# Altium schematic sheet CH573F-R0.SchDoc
size 330 x 220 mm
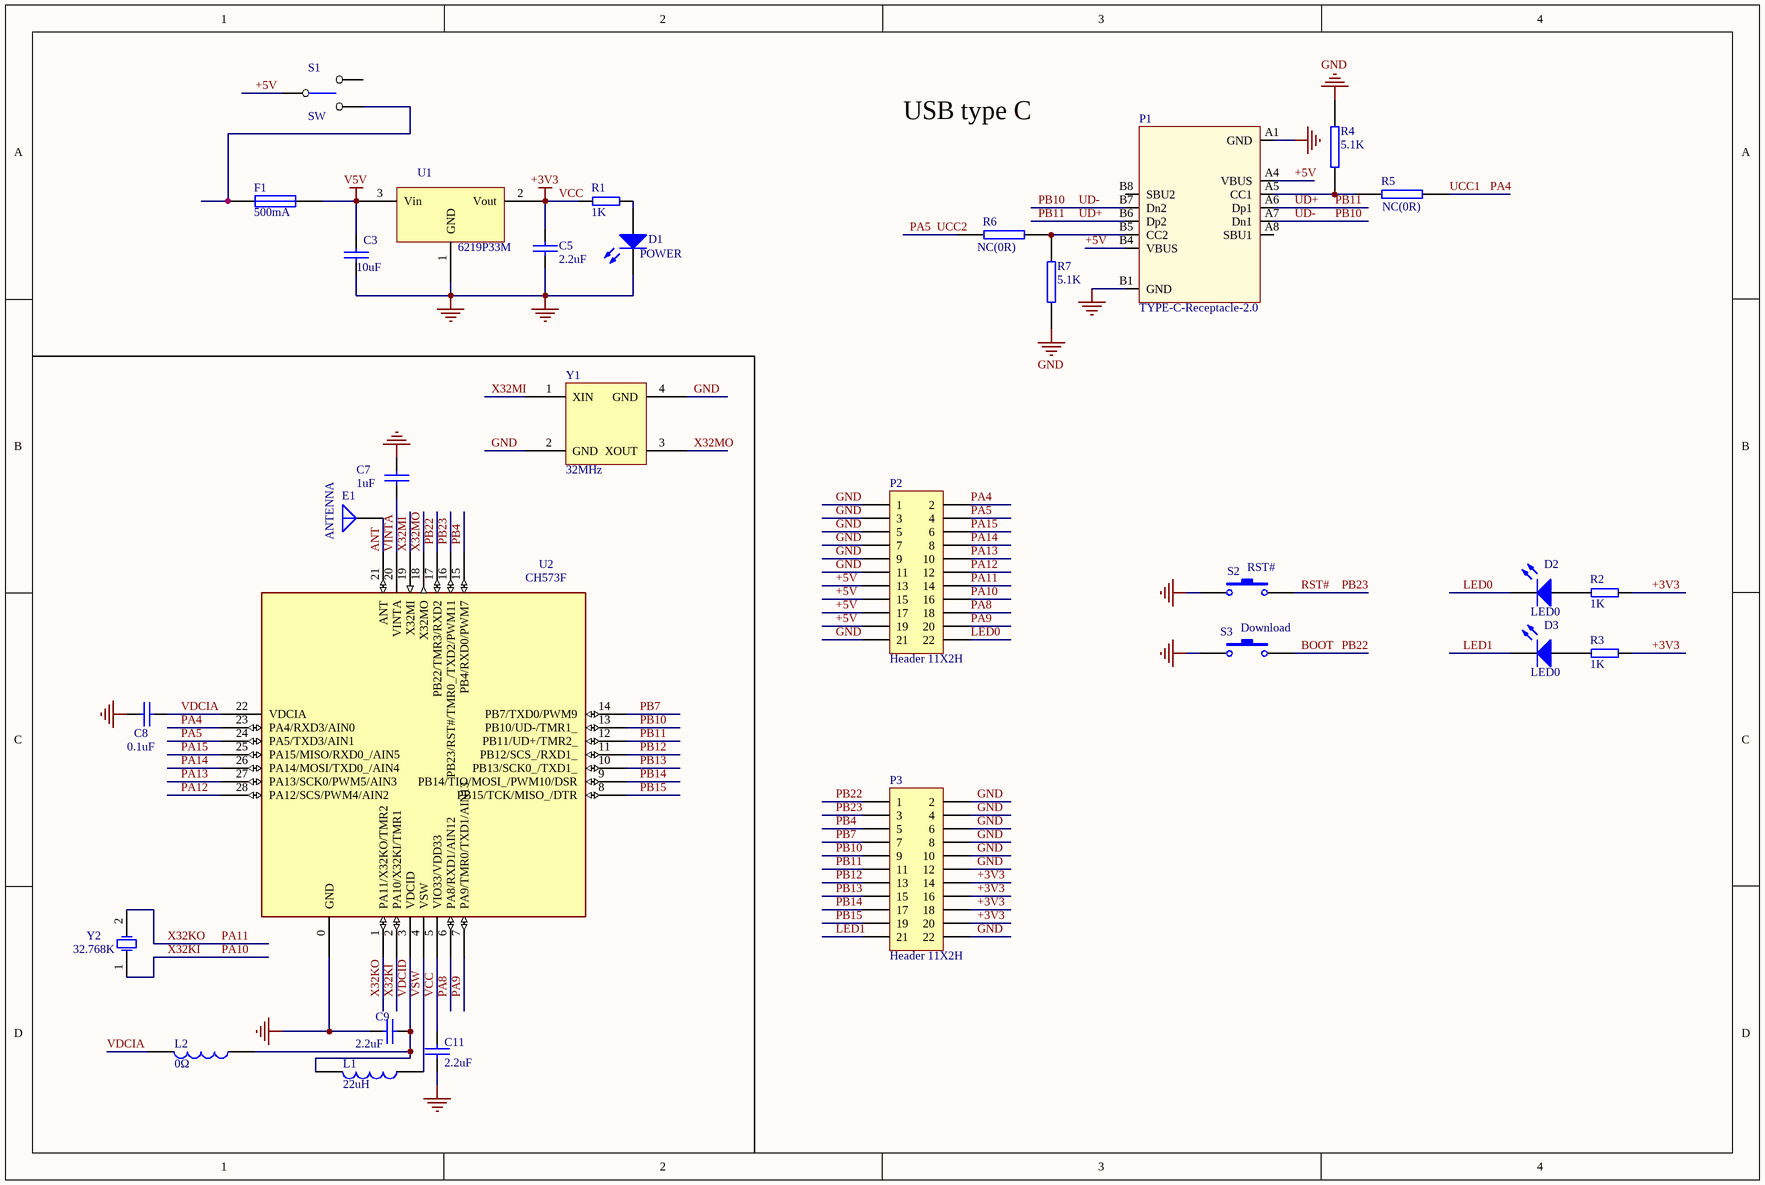
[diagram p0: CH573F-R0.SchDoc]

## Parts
C3  10uF  [3216]
C5  2.2uF  [0603]
C7  1uF  [0402]
C8  0.1uF  [0402]
C9  2.2uF  [0402]
C11  2.2uF  [0402]
D1  POWER  [0603+]
D2  LED0  [0603+]
D3  LED0  [0603+]
E1  ANTENNA  [ANT-F-1-2.4G-1.6]
F1  500mA  [0603]
L1  22uH  [L2.2]
L2  0Ω  [0603]
P1  TYPE-C-Receptacle-2.0  [TYPE-C-Receptacle-2.0]
P2  Header 11X2H  [IDC22]
P3  Header 11X2H  [IDC22]
R1  1K  [0603]
R2  1K  [0603]
R3  1K  [0603]
R4  5.1K  [0603]
R5  NC(0R)  [0603]
R6  NC(0R)  [0603]
R7  5.1K  [0603]
S1  SW  [Horizontal Slide Switch-8.7*4.4MM-2D]
S2  RST#  [KEY-SMD-6.1*3.65*2.5]
S3  Download  [KEY-SMD-6.1*3.65*2.5]
U1  6219P33M  [SOT-23]
U2  CH573F  [QFN28_4X4]
Y1  32MHz  [3225]
Y2  32.768K  [fc-135]

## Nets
+3V3: C5.1 C11.2 P3.14 P3.16 P3.18 P3.20 R1.2 R2.2 R3.2 U1.2(Vout) U2.5(VIO33/VDD33)  [also labelled VCC]
GND: C3.2 C5.2 C7.2 C8.2 C9.1 C11.1 D1.2(K) P1.A1(GND) P1.B1(GND) P2.1 P2.3 P2.5 P2.7 P2.9 P2.11 P2.21 P3.2 P3.4 P3.6 P3.8 P3.10 P3.12 P3.22 R4.2 R7.1 S2.1 S3.1 U1.1(GND) U2.0(GND) Y1.2(GND) Y1.4(GND)
V5V: C3.1 F1.2 U1.3(Vin)
+5V: P1.A4(VBUS) P1.B4(VBUS) P2.13 P2.15 P2.17 P2.19 S1.1
ANT: E1.1(A) U2.21(ANT)
BOOT: P3.1 S3.2 U2.17(PB22/TMR3/RXD2)  [also labelled PB22]
LED0: D2.2(K) P2.22
LED1: D3.2(K) P3.21
PA4: P2.2 R5.2 U2.23(PA4/RXD3/AIN0)  [also labelled UCC1]
PA5: P2.4 R6.1 U2.24(PA5/TXD3/AIN1)  [also labelled UCC2]
PA8: P2.18 U2.6(PA8/RXD1/AIN12)
PA9: P2.20 U2.7(PA9/TMR0/TXD1/AIN13)
PA10: P2.16 U2.2(PA10/X32KI/TMR1) Y2.1(OSC1)  [also labelled X32KI]
PA11: P2.14 U2.1(PA11/X32KO/TMR2) Y2.2(OSC2)  [also labelled X32KO]
PA12: P2.12 U2.28(PA12/SCS/PWM4/AIN2)
PA13: P2.10 U2.27(PA13/SCK0/PWM5/AIN3)
PA14: P2.8 U2.26(PA14/MOSI/TXD0_/AIN4)
PA15: P2.6 U2.25(PA15/MISO/RXD0_/AIN5)
PB4: P3.5 U2.15(PB4/RXD0/PWM7)
PB7: P3.7 U2.14(PB7/TXD0/PWM9)
PB10: P1.A7(Dn1) P1.B7(Dn2) P3.9 U2.13(PB10/UD-/TMR1_)  [also labelled UD-]
PB11: P1.A6(Dp1) P1.B6(Dp2) P3.11 U2.12(PB11/UD+/TMR2_)  [also labelled UD+]
PB12: P3.13 U2.11(PB12/SCS_/RXD1_)
PB13: P3.15 U2.10(PB13/SCK0_/TXD1_)
PB14: P3.17 U2.9(PB14/TIO/MOSI_/PWM10/DSR)
PB15: P3.19 U2.8(PB15/TCK/MISO_/DTR)
PB23: P3.3 S2.2 U2.16(PB23/RST#/TMR0_/TXD2/PWM11)  [also labelled RST#]
VDCIA: C8.1 L2.2 U2.22(VDCIA)
VDCID: C9.2 L1.2 L2.1 U2.3(VDCID)
VINTA: C7.1 U2.20(VINTA)
VSW: L1.1 U2.4(VSW)
X32MI: U2.19(X32MI) Y1.1(XIN)
X32MO: U2.18(X32MO) Y1.3(XOUT)
NetD1_1: D1.1(A) R1.1
NetD2_1: D2.1(A) R2.1
NetD3_1: D3.1(A) R3.1
NetF1_1: F1.1 S1.2
NetP1_A5: P1.A5(CC1) R4.1 R5.1
NetP1_B5: P1.B5(CC2) R6.2 R7.2

Not connected (* = marked no-connect by the designer): P1 A8(SBU1) B8(SBU2); S1 3

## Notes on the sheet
- USB type C

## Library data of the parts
C3 C5 C7-C9 C11 = CAP: Capacitor
D1-D3 = LED0: Typical INFRARED GaAs LED
E1 = ANTENNA: Generic Antenna
F1 = FUSE1: Fuse
L1 L2 = INDUCTOR
P1 = TYPE-C-Receptacle-2.0: Type-C USB2.0 母座
P2 P3 = Header 11X2H: Header, 11-Pin, Dual row, Right Angle
R1-R3 = RES
R4-R7 = RES2
S2 S3 = SW-PB: Switch
U2 = CH573F: RISC-V MCU with BLE/USB/ADC/SPI/4*UART
Y1 = 晶体
Y2 = XTAL: Crystal Oscillator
